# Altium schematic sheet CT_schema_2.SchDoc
size 313 x 200 mm
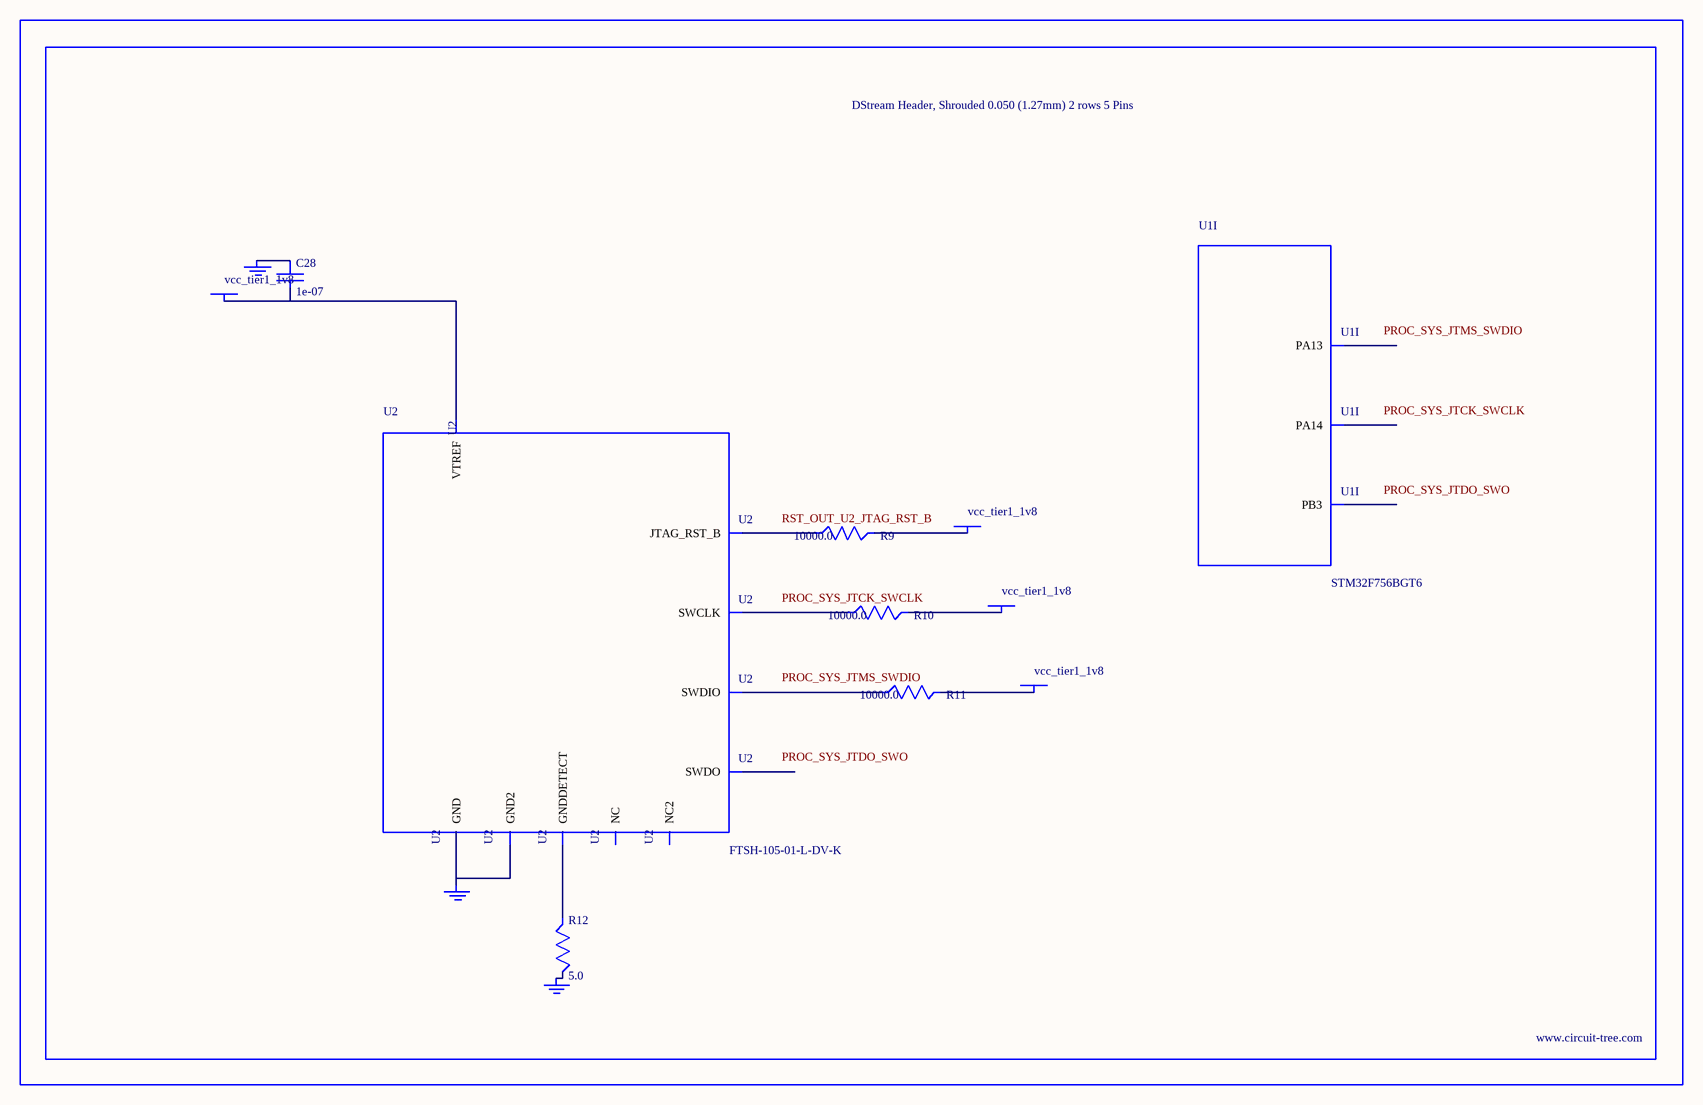
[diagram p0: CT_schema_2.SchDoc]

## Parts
BORDER1  (no value)
C28  1e-07  [C0402]
GND_INSTANCE_1_0  (no value)
GND_INSTANCE_1_1  (no value)
GND_INSTANCE_1_2  (no value)
POWER_INSTANCE_1_0  vcc_tier1_1v8
POWER_INSTANCE_1_1  vcc_tier1_1v8
POWER_INSTANCE_1_2  vcc_tier1_1v8
POWER_INSTANCE_1_3  vcc_tier1_1v8
R9  10000.0  [R0603]
R10  10000.0  [R0603]
R11  10000.0  [R0603]
R12  5.0  [R0603]
U1  STM32F756BGT6  [LQFP208]  (part I of 15)
U2  FTSH-105-01-L-DV-K  [SAMTEC_FTSH-105-01-L-DV-K]

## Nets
NetC28_1: C28.1 GND_INSTANCE_1_0.0(GND)
NetC28_2: C28.2 POWER_INSTANCE_1_0.0(PWR) U2.1(VTREF)
NetGND_INSTANCE_1_1_0: GND_INSTANCE_1_1.0(GND) R12.2
NetGND_INSTANCE_1_2_0: GND_INSTANCE_1_2.0(GND) U2.3(GND) U2.5(GND2)
NetPOWER_INSTANCE_1_1_0: POWER_INSTANCE_1_1.0(PWR) R11.2
NetPOWER_INSTANCE_1_2_0: POWER_INSTANCE_1_2.0(PWR) R10.2
NetPOWER_INSTANCE_1_3_0: POWER_INSTANCE_1_3.0(PWR) R9.2
NetR9_1: R9.1 U2.10(JTAG_RST_B)
NetR10_1: R10.1 U2.4(SWCLK)
NetR11_1: R11.1 U2.2(SWDIO)
NetR12_1: R12.1 U2.9(GNDDETECT)

Not connected (* = marked no-connect by the designer): U1 147(PA13) 159(PA14) 192(PB3); U2 6(SWDO) 7(NC) 8(NC2)

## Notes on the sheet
- Labels drawn without touching a wire or pin: PROC_SYS_JTCK_SWCLK, PROC_SYS_JTDO_SWO, PROC_SYS_JTMS_SWDIO, RST_OUT_U2_JTAG_RST_B

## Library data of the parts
BORDER1 = BORDER_PAGE1
C28 = C0402C104K3RACTU
GND_INSTANCE_1_0-GND_INSTANCE_1_2 = GND
POWER_INSTANCE_1_0-POWER_INSTANCE_1_3 = PWR
R9-R11 = RC0603JR-0710KL
R12 = ERJ-3GEYJ5R1V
